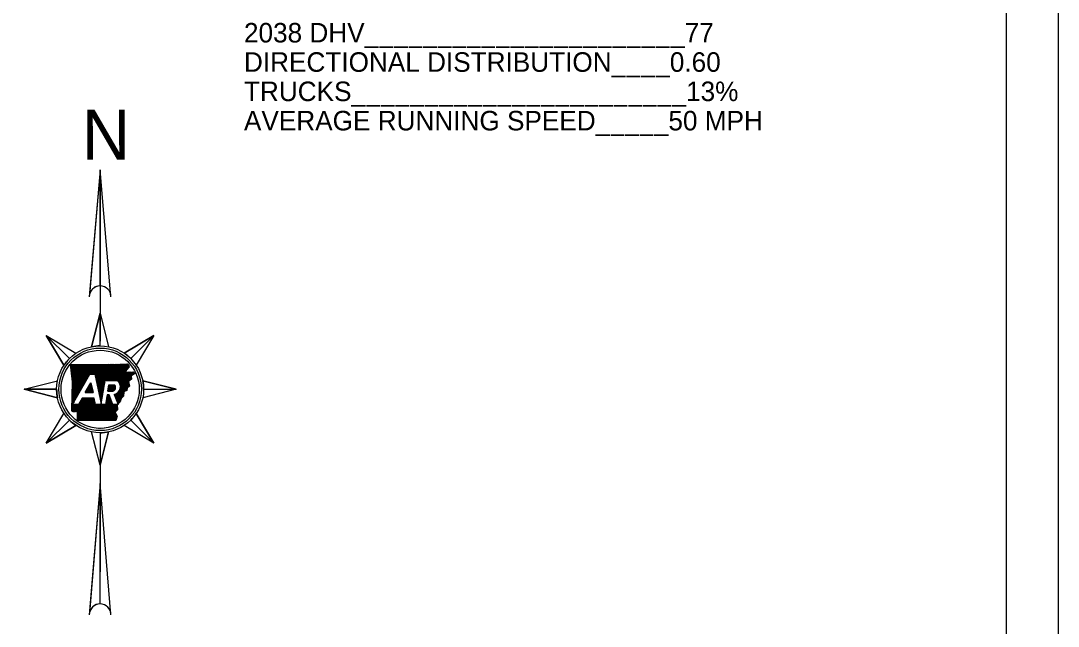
# Model space of a CAD drawing. Extents: x 1369979 to 1371646, y 379997 to 381064.
# Drawn here: x 1371168.2 to 1371645.6, y 380245.7 to 380524.5 of the extents above; entities that cross this region are included whole.
import ezdxf

# ---------------------------------------------------------------- set-up
doc = ezdxf.new("R2010")
doc.units = 0
for name, color, linetype in [('R_Border', 7, 'Continuous'), ('R_Draft', 7, 'Continuous'), ('R_No Plot', 7, 'Continuous'), ('R_Water Annot', 7, 'Continuous')]:
    doc.layers.add(name, color=color, linetype=linetype)

msp = doc.modelspace()

# ---------------------------------------------------------------- linework, layer by layer
at = {"layer": 'R_Border'}
msp.add_line((1371621.85, 380017.3), (1371621.85, 381044.6), dxfattribs=at)
at = {"layer": 'R_Draft'}
for p, q in [((1371204.74, 380455.94), (1371199.81, 380398.28)), ((1371204.74, 380455.94), (1371204.74, 380376.98)), ((1371204.74, 380402.44), (1371204.74, 380455.94)), ((1371199.88, 380399.09), (1371200.1, 380399.31)), ((1371199.9, 380399.4), (1371200.36, 380399.85)), ((1371204.74, 380389.8), (1371200.84, 380374.41)), ((1371204.74, 380374.8), (1371204.74, 380389.8)), ((1371179.99, 380379.54), (1371190.59, 380368.94)), ((1371190.59, 380368.94), (1371179.99, 380379.54)), ((1371179.99, 380379.54), (1371188.11, 380365.91)), ((1371229.48, 380379.54), (1371215.85, 380371.42)), ((1371218.88, 380368.94), (1371229.48, 380379.54)), ((1371218.88, 380368.94), (1371229.48, 380379.54)), ((1371192.1, 380347.79), (1371200, 380361.73)), ((1371200, 380361.73), (1371202.34, 380361.73)), ((1371169.74, 380354.8), (1371184.74, 380354.8)), ((1371184.74, 380354.8), (1371169.74, 380354.8)), ((1371169.74, 380354.8), (1371185.12, 380350.9)), ((1371197.91, 380353.26), (1371200.49, 380357.82)), ((1371207.1, 380358.82), (1371212.58, 380358.82)), ((1371208.81, 380356.85), (1371211.38, 380356.85)), ((1371239.74, 380354.8), (1371224.35, 380358.69)), ((1371224.74, 380354.8), (1371239.74, 380354.8)), ((1371224.74, 380354.8), (1371239.74, 380354.8)), ((1371196.47, 380350.71), (1371194.81, 380347.79)), ((1371202.01, 380350.71), (1371196.47, 380350.71)), ((1371197.91, 380353.26), (1371201.47, 380353.26)), ((1371208.95, 380352.22), (1371208, 380352.22)), ((1371208.29, 380353.88), (1371210.64, 380353.88)), ((1371210.59, 380347.79), (1371208.95, 380352.22)), ((1371211.27, 380352.46), (1371213, 380347.79)), ((1371194.81, 380347.79), (1371192.1, 380347.79)), ((1371207.23, 380347.79), (1371202.64, 380347.79)), ((1371213, 380347.79), (1371210.59, 380347.79)), ((1371179.99, 380330.05), (1371190.59, 380340.65)), ((1371190.59, 380340.65), (1371179.99, 380330.05)), ((1371218.88, 380340.65), (1371229.48, 380330.05)), ((1371218.88, 380340.65), (1371229.48, 380330.05)), ((1371229.48, 380330.05), (1371221.36, 380343.68)), ((1371179.99, 380330.05), (1371193.62, 380338.17)), ((1371204.73, 380334.8), (1371204.74, 380334.8)), ((1371204.74, 380319.8), (1371208.63, 380335.18)), ((1371204.74, 380334.8), (1371204.74, 380270.77)), ((1371204.74, 380334.8), (1371204.74, 380319.8)), ((1371204.74, 380311.44), (1371199.8, 380251.76)), ((1371204.74, 380255.94), (1371204.74, 380311.44))]:
    msp.add_line(p, q, dxfattribs=at)
for points in [[(1371209.74, 380397.44), (1371204.74, 380455.94), (1371199.74, 380397.44)], [(1371200.84, 380374.41), (1371204.74, 380389.8), (1371208.63, 380374.41)], [(1371188.11, 380365.91), (1371179.99, 380379.54), (1371193.62, 380371.42)], [(1371215.85, 380371.42), (1371229.48, 380379.54), (1371221.36, 380365.91)], [(1371191.08, 380366.24), (1371198.89, 380366.24), (1371205.73, 380366.25), (1371213.81, 380366.38), (1371217.56, 380366.47)], [(1371191.65, 380345.13), (1371192.08, 380358.22), (1371191.08, 380366.24)], [(1371202.34, 380361.73), (1371205.24, 380348.16), (1371207.1, 380358.82)], [(1371220.01, 380362.88), (1371220.69, 380362.17), (1371219, 380360.79), (1371219.18, 380359.39), (1371217.74, 380358.44), (1371218.23, 380356.29), (1371217.12, 380355.28), (1371217.02, 380354.17), (1371215.67, 380353.69), (1371215.46, 380351.6), (1371214.49, 380350.56), (1371214.01, 380348.99), (1371212.6, 380347.7), (1371212.71, 380345.41), (1371211.74, 380344.33), (1371212.62, 380342.37), (1371212.01, 380340.42)], [(1371216.4, 380362.7), (1371220.06, 380362.89)], [(1371185.12, 380350.9), (1371169.74, 380354.8), (1371185.12, 380358.69)], [(1371200.49, 380357.82), (1371201.47, 380353.26)], [(1371208.29, 380353.88), (1371208.81, 380356.85)], [(1371224.35, 380358.69), (1371239.74, 380354.8), (1371224.35, 380350.9)], [(1371202.64, 380347.79), (1371202.01, 380350.71)], [(1371208, 380352.22), (1371207.23, 380347.79)], [(1371193.62, 380338.17), (1371179.99, 380330.05), (1371188.11, 380343.68)], [(1371212.01, 380340.42), (1371194.32, 380340.45), (1371194.32, 380344.35)], [(1371221.36, 380343.68), (1371229.48, 380330.05), (1371215.85, 380338.17)], [(1371208.63, 380335.18), (1371204.74, 380319.8), (1371200.84, 380335.18)], [(1371209.74, 380250.94), (1371204.74, 380311.44), (1371199.74, 380250.94)]]:
    msp.add_lwpolyline(points, dxfattribs=at)
for radius in [20, 18]:
    msp.add_circle((1371204.74, 380354.8), radius, dxfattribs=at)
for centre, radius, start, end in [((1371204.74, 380397.44), 5, 0, 180), ((1371204.74, 380397.44), 5, 90, 170.2296), ((1371204.74, 380354.8), 20, 90, 101.2291), ((1371204.74, 380354.8), 20, 135, 146.2291), ((1371204.74, 380354.8), 20, 45, 56.2291), ((1371204.74, 380354.8), 20, 180, 191.2291), ((1371210.08, 380355.6), 1.81, 288.1268, 43.8902), ((1371210.54, 380355.92), 3.54, 281.8626, 54.8705), ((1371204.74, 380354.8), 20, 0, 11.2291), ((1371204.74, 380354.8), 20, 225, 236.2291), ((1371204.74, 380354.8), 20, 315, 326.2291), ((1371204.74, 380354.8), 20, 270, 281.2291), ((1371204.74, 380250.94), 5, 0, 180), ((1371204.74, 380250.94), 5, 90, 170.5511)]:
    msp.add_arc(centre, radius, start, end, dxfattribs=at)
for points in [[(1371217.56, 380366.47), (1371217.58, 380366.25), (1371217.65, 380366.14), (1371217.66, 380365.94), (1371217.74, 380365.85), (1371217.88, 380365.77), (1371218.01, 380365.63), (1371218.04, 380365.46), (1371218, 380365.29), (1371217.99, 380365.11), (1371217.97, 380364.94), (1371217.94, 380364.79), (1371217.82, 380364.67), (1371217.71, 380364.58), (1371217.61, 380364.48), (1371217.54, 380364.38), (1371217.41, 380364.26), (1371217.29, 380364.14), (1371217.19, 380364.03), (1371217.09, 380363.9), (1371217.04, 380363.75), (1371216.93, 380363.64), (1371216.84, 380363.55), (1371216.72, 380363.42), (1371216.67, 380363.29), (1371216.55, 380363.14), (1371216.53, 380362.99), (1371216.46, 380362.88), (1371216.45, 380362.86)], [(1371194.32, 380344.35), (1371194.33, 380344.34), (1371194.24, 380344.4), (1371194.12, 380344.47), (1371193.98, 380344.48), (1371193.8, 380344.5), (1371193.65, 380344.52), (1371193.49, 380344.62), (1371193.33, 380344.51), (1371193.15, 380344.43), (1371193.04, 380344.52), (1371192.9, 380344.46), (1371192.8, 380344.49), (1371192.64, 380344.38), (1371192.48, 380344.42), (1371192.36, 380344.39), (1371192.22, 380344.39), (1371192.19, 380344.55), (1371192.05, 380344.58), (1371191.93, 380344.65), (1371191.84, 380344.82), (1371191.79, 380344.95), (1371191.65, 380345.13)]]:
    msp.add_spline(points, degree=3, dxfattribs=at)
at = {"layer": 'R_No Plot'}
msp.add_lwpolyline([(1369978.91, 381064.07), (1371645.61, 381064.07), (1371645.61, 379997.39), (1369978.91, 379997.39)], close=True, dxfattribs=at)
at = {"layer": 'R_Water Annot'}
for p, q in [((1371191.1, 380366.07), (1371191.28, 380366.24)), ((1371191.17, 380365.56), (1371191.85, 380366.24)), ((1371191.23, 380365.06), (1371192.41, 380366.24)), ((1371191.29, 380364.56), (1371192.98, 380366.24)), ((1371191.35, 380364.06), (1371193.54, 380366.24)), ((1371191.42, 380363.55), (1371194.11, 380366.24)), ((1371191.48, 380363.05), (1371194.67, 380366.24)), ((1371191.54, 380362.55), (1371195.24, 380366.24)), ((1371191.6, 380362.04), (1371195.8, 380366.24)), ((1371191.67, 380361.54), (1371196.37, 380366.24)), ((1371191.73, 380361.04), (1371196.93, 380366.24)), ((1371191.79, 380360.53), (1371197.5, 380366.24)), ((1371191.86, 380360.03), (1371198.06, 380366.24)), ((1371191.92, 380359.53), (1371198.63, 380366.24)), ((1371191.94, 380353.89), (1371204.3, 380366.25)), ((1371191.96, 380354.48), (1371203.73, 380366.25)), ((1371191.98, 380355.06), (1371203.16, 380366.25)), ((1371191.98, 380359.03), (1371199.2, 380366.24)), ((1371191.99, 380355.65), (1371202.6, 380366.25)), ((1371192.01, 380356.23), (1371202.03, 380366.25)), ((1371192.03, 380356.82), (1371201.46, 380366.24)), ((1371192.04, 380358.52), (1371199.76, 380366.24)), ((1371192.05, 380357.4), (1371200.9, 380366.24)), ((1371192.07, 380357.99), (1371200.33, 380366.24)), ((1371200.34, 380361.73), (1371204.86, 380366.25)), ((1371200.9, 380361.73), (1371205.43, 380366.25)), ((1371201.47, 380361.73), (1371206, 380366.26)), ((1371202.03, 380361.73), (1371206.58, 380366.27)), ((1371202.39, 380361.51), (1371207.15, 380366.28)), ((1371202.49, 380361.05), (1371207.73, 380366.28)), ((1371202.59, 380360.58), (1371208.3, 380366.29)), ((1371202.69, 380360.11), (1371208.87, 380366.3)), ((1371202.79, 380359.65), (1371209.45, 380366.31)), ((1371202.89, 380359.18), (1371210.02, 380366.32)), ((1371202.98, 380358.72), (1371210.6, 380366.33)), ((1371203.08, 380358.25), (1371211.17, 380366.34)), ((1371203.18, 380357.78), (1371211.75, 380366.35)), ((1371203.28, 380357.32), (1371212.32, 380366.36)), ((1371203.38, 380356.85), (1371212.9, 380366.37)), ((1371203.48, 380356.39), (1371213.47, 380366.37)), ((1371203.58, 380355.92), (1371214.05, 380366.38)), ((1371203.68, 380355.45), (1371214.63, 380366.4)), ((1371207.61, 380358.82), (1371215.21, 380366.41)), ((1371208.18, 380358.82), (1371215.79, 380366.43)), ((1371208.74, 380358.82), (1371216.36, 380366.44)), ((1371209.31, 380358.82), (1371216.94, 380366.45)), ((1371209.88, 380358.82), (1371217.52, 380366.47)), ((1371210.44, 380358.82), (1371217.65, 380366.03)), ((1371211.01, 380358.82), (1371217.92, 380365.73)), ((1371211.57, 380358.82), (1371218, 380365.24)), ((1371191.9, 380352.72), (1371198.81, 380359.63)), ((1371191.92, 380353.31), (1371199.55, 380360.94)), ((1371212.14, 380358.82), (1371216.7, 380363.38)), ((1371212.65, 380358.77), (1371216.59, 380362.71)), ((1371212.96, 380358.51), (1371217.19, 380362.74)), ((1371213.24, 380358.22), (1371217.78, 380362.77)), ((1371213.48, 380357.9), (1371218.38, 380362.8)), ((1371213.69, 380357.54), (1371218.98, 380362.83)), ((1371213.86, 380357.15), (1371219.57, 380362.86)), ((1371213.96, 380354.98), (1371219.09, 380360.11)), ((1371213.99, 380356.71), (1371220.11, 380362.83)), ((1371214.07, 380356.23), (1371220.38, 380362.53)), ((1371214.07, 380355.66), (1371219.03, 380360.61)), ((1371218.46, 380358.91), (1371219.16, 380359.61)), ((1371220.12, 380361.71), (1371220.64, 380362.23)), ((1371191.82, 380350.38), (1371195.86, 380354.42)), ((1371191.84, 380350.96), (1371196.6, 380355.72)), ((1371191.86, 380351.55), (1371197.34, 380357.03)), ((1371191.88, 380352.14), (1371198.07, 380358.33)), ((1371197.94, 380353.26), (1371200.84, 380356.17)), ((1371198.5, 380353.26), (1371200.94, 380355.7)), ((1371198.61, 380354.5), (1371200.74, 380356.63)), ((1371199.07, 380353.26), (1371201.04, 380355.23)), ((1371199.35, 380355.8), (1371200.64, 380357.1)), ((1371199.63, 380353.26), (1371201.14, 380354.77)), ((1371200.09, 380357.11), (1371200.54, 380357.56)), ((1371203.78, 380354.99), (1371206.99, 380358.2)), ((1371203.88, 380354.52), (1371206.87, 380357.51)), ((1371203.98, 380354.06), (1371206.75, 380356.83)), ((1371204.08, 380353.59), (1371206.63, 380356.14)), ((1371204.18, 380353.12), (1371206.51, 380355.46)), ((1371204.28, 380352.66), (1371206.4, 380354.77)), ((1371208.29, 380353.88), (1371211.27, 380356.85)), ((1371208.41, 380354.56), (1371210.7, 380356.85)), ((1371208.53, 380355.24), (1371210.14, 380356.85)), ((1371208.65, 380355.93), (1371209.57, 380356.85)), ((1371208.77, 380356.61), (1371209.01, 380356.85)), ((1371208.86, 380353.88), (1371211.58, 380356.6)), ((1371209.42, 380353.88), (1371211.77, 380356.23)), ((1371209.99, 380353.88), (1371211.88, 380355.76)), ((1371210.56, 380353.88), (1371211.83, 380355.15)), ((1371211.62, 380351.51), (1371217.89, 380357.78)), ((1371211.77, 380351.1), (1371218, 380357.32)), ((1371211.93, 380350.69), (1371218.1, 380356.86)), ((1371212.08, 380350.27), (1371218.21, 380356.4)), ((1371213.46, 380353.92), (1371217.79, 380358.24)), ((1371216.28, 380353.9), (1371217.07, 380354.7)), ((1371191.76, 380348.62), (1371193.64, 380350.51)), ((1371191.78, 380349.21), (1371194.38, 380351.81)), ((1371191.8, 380349.79), (1371195.12, 380353.11)), ((1371191.87, 380344.77), (1371197.81, 380350.71)), ((1371192.2, 380344.54), (1371198.38, 380350.71)), ((1371192.61, 380344.38), (1371198.94, 380350.71)), ((1371193.28, 380344.49), (1371199.51, 380350.71)), ((1371193.85, 380344.49), (1371200.07, 380350.71)), ((1371194.3, 380344.37), (1371200.64, 380350.71)), ((1371194.32, 380343.26), (1371201.77, 380350.71)), ((1371194.32, 380343.82), (1371201.2, 380350.71)), ((1371194.32, 380342.7), (1371202.07, 380350.45)), ((1371194.32, 380342.13), (1371202.17, 380349.98)), ((1371195.45, 380348.92), (1371197.24, 380350.71)), ((1371196.19, 380350.23), (1371196.68, 380350.71)), ((1371199.98, 380340.44), (1371209.71, 380350.17)), ((1371200.2, 380353.26), (1371201.24, 380354.3)), ((1371200.55, 380340.44), (1371209.86, 380349.75)), ((1371200.77, 380353.26), (1371201.34, 380353.84)), ((1371201.33, 380353.26), (1371201.44, 380353.37)), ((1371204.38, 380352.19), (1371206.28, 380354.09)), ((1371204.48, 380351.73), (1371206.16, 380353.4)), ((1371204.58, 380351.26), (1371206.04, 380352.72)), ((1371204.68, 380350.79), (1371205.92, 380352.03)), ((1371204.78, 380350.33), (1371205.8, 380351.35)), ((1371204.88, 380349.86), (1371205.68, 380350.66)), ((1371204.98, 380349.4), (1371205.56, 380349.98)), ((1371207.33, 380348.35), (1371209.56, 380350.58)), ((1371207.45, 380349.04), (1371209.4, 380350.99)), ((1371207.57, 380349.72), (1371209.25, 380351.41)), ((1371207.69, 380350.41), (1371209.1, 380351.82)), ((1371207.8, 380351.09), (1371208.94, 380352.22)), ((1371207.92, 380351.78), (1371208.37, 380352.22)), ((1371211.32, 380352.34), (1371211.49, 380352.51)), ((1371211.47, 380351.93), (1371212.54, 380353)), ((1371212.23, 380349.86), (1371215.62, 380353.25)), ((1371212.38, 380349.45), (1371215.56, 380352.62)), ((1371212.54, 380349.03), (1371215.5, 380351.99)), ((1371212.69, 380348.62), (1371214.42, 380350.36)), ((1371191.65, 380345.12), (1371194.32, 380347.79)), ((1371191.66, 380345.7), (1371193.76, 380347.79)), ((1371191.68, 380346.28), (1371193.19, 380347.79)), ((1371191.7, 380346.87), (1371192.62, 380347.79)), ((1371191.72, 380347.45), (1371192.17, 380347.9)), ((1371191.74, 380348.04), (1371192.9, 380349.2)), ((1371194.32, 380341.57), (1371202.27, 380349.51)), ((1371194.32, 380341), (1371202.37, 380349.05)), ((1371194.33, 380340.45), (1371202.47, 380348.58)), ((1371194.9, 380340.45), (1371202.57, 380348.12)), ((1371195.46, 380340.45), (1371202.81, 380347.79)), ((1371196.03, 380340.44), (1371203.37, 380347.79)), ((1371196.59, 380340.44), (1371203.94, 380347.79)), ((1371197.16, 380340.44), (1371204.5, 380347.79)), ((1371197.72, 380340.44), (1371205.07, 380347.79)), ((1371198.29, 380340.44), (1371205.63, 380347.79)), ((1371198.85, 380340.44), (1371206.2, 380347.79)), ((1371199.42, 380340.44), (1371206.77, 380347.79)), ((1371201.11, 380340.44), (1371210.02, 380349.34)), ((1371201.67, 380340.44), (1371210.17, 380348.93)), ((1371202.24, 380340.43), (1371210.32, 380348.52)), ((1371202.8, 380340.43), (1371210.47, 380348.1)), ((1371203.37, 380340.43), (1371210.73, 380347.79)), ((1371203.93, 380340.43), (1371211.29, 380347.79)), ((1371204.5, 380340.43), (1371211.86, 380347.79)), ((1371205.06, 380340.43), (1371212.42, 380347.79)), ((1371205.08, 380348.93), (1371205.44, 380349.29)), ((1371205.18, 380348.46), (1371205.32, 380348.61)), ((1371205.63, 380340.43), (1371212.61, 380347.41)), ((1371206.19, 380340.43), (1371212.64, 380346.87)), ((1371206.76, 380340.43), (1371212.66, 380346.33)), ((1371207.32, 380340.43), (1371212.69, 380345.79)), ((1371212.84, 380348.21), (1371214.18, 380349.55)), ((1371207.89, 380340.43), (1371211.76, 380344.3)), ((1371208.45, 380340.42), (1371211.93, 380343.91)), ((1371209.02, 380340.42), (1371212.11, 380343.51)), ((1371209.58, 380340.42), (1371212.28, 380343.12)), ((1371210.15, 380340.42), (1371212.46, 380342.73)), ((1371210.71, 380340.42), (1371212.6, 380342.31)), ((1371211.28, 380340.42), (1371212.35, 380341.49)), ((1371211.84, 380340.42), (1371212.09, 380340.67))]:
    msp.add_line(p, q, dxfattribs=at)
msp.add_circle((1371204.74, 380354.8), 19, dxfattribs=at)

# ---------------------------------------------------------------- texts
at = {"layer": 'R_Draft'}
for s, height, p in [('2038 DHV______________________77', 9, (1371270.93, 380514.52)), ('DIRECTIONAL DISTRIBUTION____0.60', 9, (1371270.93, 380501.02)), ('TRUCKS_______________________13%', 9, (1371270.93, 380487.52)), ('N', 23.08, (1371196.3, 380460.48)), ('AVERAGE RUNNING SPEED_____50 MPH', 9, (1371270.93, 380474.02)), ('DWB 7-27-17', 0.3889, (1371203.51, 380336.46))]:
    msp.add_text(s, height=height, dxfattribs=at).set_placement(p)

doc.saveas('drawing.dxf')
